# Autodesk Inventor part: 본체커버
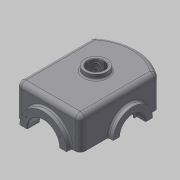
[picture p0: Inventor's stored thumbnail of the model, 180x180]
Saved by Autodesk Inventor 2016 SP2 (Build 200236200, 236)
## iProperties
Created: 2019-03
Part Number: 본체커버
Material: 일반
Document SubType Name: Modeling
Designer: mduedu
Density: 1 g/cm^3
Mass: 543.443 g
Surface Area: 1101.4 cm^2
Volume: 543.443 cm^3
Appearance: 기본값
Author: mduedu
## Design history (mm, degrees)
sketch "스케치1"
  geometry: L1 (90, -65)-(-65.993, -65); L2 (-65.993, 65)-(90, 65); L3 (90, 65)-(90, -65); L4 (-90, 0)-(90, 0); A1 r 100 centre (10, 0) between (-65.993, 65) and (-65.993, -65); 2 further points
  constraints: 8 end point, 3 point on circle, 2 horizontal alignment, 2 midpoint, 1 centre point, 1 coincident, 1 horizontal, 1 parallel, 1 perpendicular
  dimensions: "d0" = 100 radius of A1; "d2" = 180 distance from line of L3 L4.start; "d3" = 130 distance between parallel lines of L2 L1
extrude "돌출1" new body sketch "스케치1" distance "d4" = 65; taper "d5" = 0 deg
fillet "모깎기1" dims "d6" = 10
fillet "모깎기2" dims "d7" = 10
feature "쉘1" dims "d8" = 10, "d79" = 15
fillet "모깎기3" dims "d9" = 3
fillet "모깎기4" dims "d10" = 3
sketch "스케치2"
  geometry: L1 (110, 0)-(0, 0) reference; A1 r 47.5 centre (55, 0) between (102.5, 0) and (7.5, 0); 1 further point
  constraints: 2 point on circle, 2 point on line, 1 centre point, 1 coincident
  dimensions: "d11" = 95 diameter of A1
extrude "돌출2" join sketch "스케치2" distance "d12" = 10; taper "d13" = 0 deg
hole "구멍1" diameter "d16" = 65; stored, may be unused: countersink angle "d20" = 90 deg, drill point angle "d22" = 118 deg; dims "d14" = 10, "d15" = 10, "d17" = 6, "d18" = 4, "d19" = 2, "d21" = 8
node "작업 평면1"
sketch "스케치3"
  geometry: L1 (61.239, 0)-(-80, 0) reference; L2 (-100, 47.5)-(-100, 0) reference; A1 r 40 centre (7, 0) between (47, 0) and (-33, 0); 1 further point
  constraints: 2 point on circle, 2 point on line, 1 centre point, 1 horizontal alignment
  dimensions: "d24" = 80 diameter of A1; "d25" = 107 distance from line of A1.centre L2
extrude "돌출3" join sketch "스케치3" stored distance "d26" = 10; taper "d27" = 0 deg
hole "구멍2" diameter "d30" = 42; stored, may be unused: countersink angle "d34" = 90 deg, drill point angle "d36" = 118 deg; dims "d28" = 10, "d29" = 10, "d31" = 6, "d32" = 52, "d33" = 18, "d35" = 8
sketch "스케치4" dims "d37" = 65
  geometry: A1 r 40 centre (7, 0) between (47, 0) and (-33, 0) reference; 3 further points
  constraints: 2 vertical alignment, 1 coincident, 2 other
hole "구멍3" sketch "스케치4" at (7, 32.5) diameter "d38" = 3.242; stored, may be unused: countersink angle "d42" = 90 deg, drill point angle "d44" = 118 deg; dims "d39" = 11, "d40" = 52, "d41" = 18, "d43" = 13
sketch "스케치5" dims "d45" = 80
  geometry: A1 r 47.5 centre (55, 0) between (102.5, 0) and (7.5, 0) reference; 5 further points
  constraints: 2 vertical alignment, 1 coincident, 6 other
  dimensions: "d48" = 360 deg dimension on point (55, 0) point (55, -40) (derived)
hole "구멍4" sketch "스케치5" at (55, -40), (89.641, 20), (20.359, 20) diameter "d50" = 3.242; stored, may be unused: countersink angle "d54" = 90 deg, drill point angle "d56" = 118 deg; dims "d51" = 11, "d52" = 52, "d53" = 18, "d55" = 13
fillet "모깎기5" dims "d57" = 3
fillet "모깎기6" dims "d58" = 1
chamfer "모따기1" distance "d59" = 1; stored, may be unused: second distance "d60" = 2, angle "d61" = 45 deg
node "작업 평면2"
sketch "스케치6"
  geometry: L1 (-47, 75)-(33, 75) reference; L2 (-47, -75)-(33, -75) reference; L3 (-7, 75)-(-7, -75); C1 r 22.5 at (-7, 0); 1 further point
  constraints: 3 midpoint, 2 end point, 1 centre point
  dimensions: "d63" = 45 diameter of C1
extrude "돌출4" join sketch "스케치6" stored distance "d64" = 10; taper "d65" = 0 deg
hole "구멍5" diameter "d68" = 33.376; stored, may be unused: countersink angle "d72" = 90 deg, drill point angle "d74" = 118 deg; dims "d66" = 10, "d67" = 10, "d69" = 11, "d70" = 52, "d71" = 18, "d73" = 13
fillet "모깎기7" dims "d75" = 3
chamfer "모따기2" distance "d76" = 1; stored, may be unused: second distance "d77" = 2, angle "d78" = 45 deg
node "솔리드1"
mirror "대칭1"
other parameters: "d23" = 75, "d62" = 75
